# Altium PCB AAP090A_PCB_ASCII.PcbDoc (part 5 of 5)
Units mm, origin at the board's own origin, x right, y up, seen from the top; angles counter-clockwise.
Board outline 160 x 130 mm, 4 copper layers (Top Layer, Signal Layer 1, Signal Layer 2, Bottom Layer), stack 1.567 mm thick; 507 components, 275 nets, 1462 pads, 1041 vias.
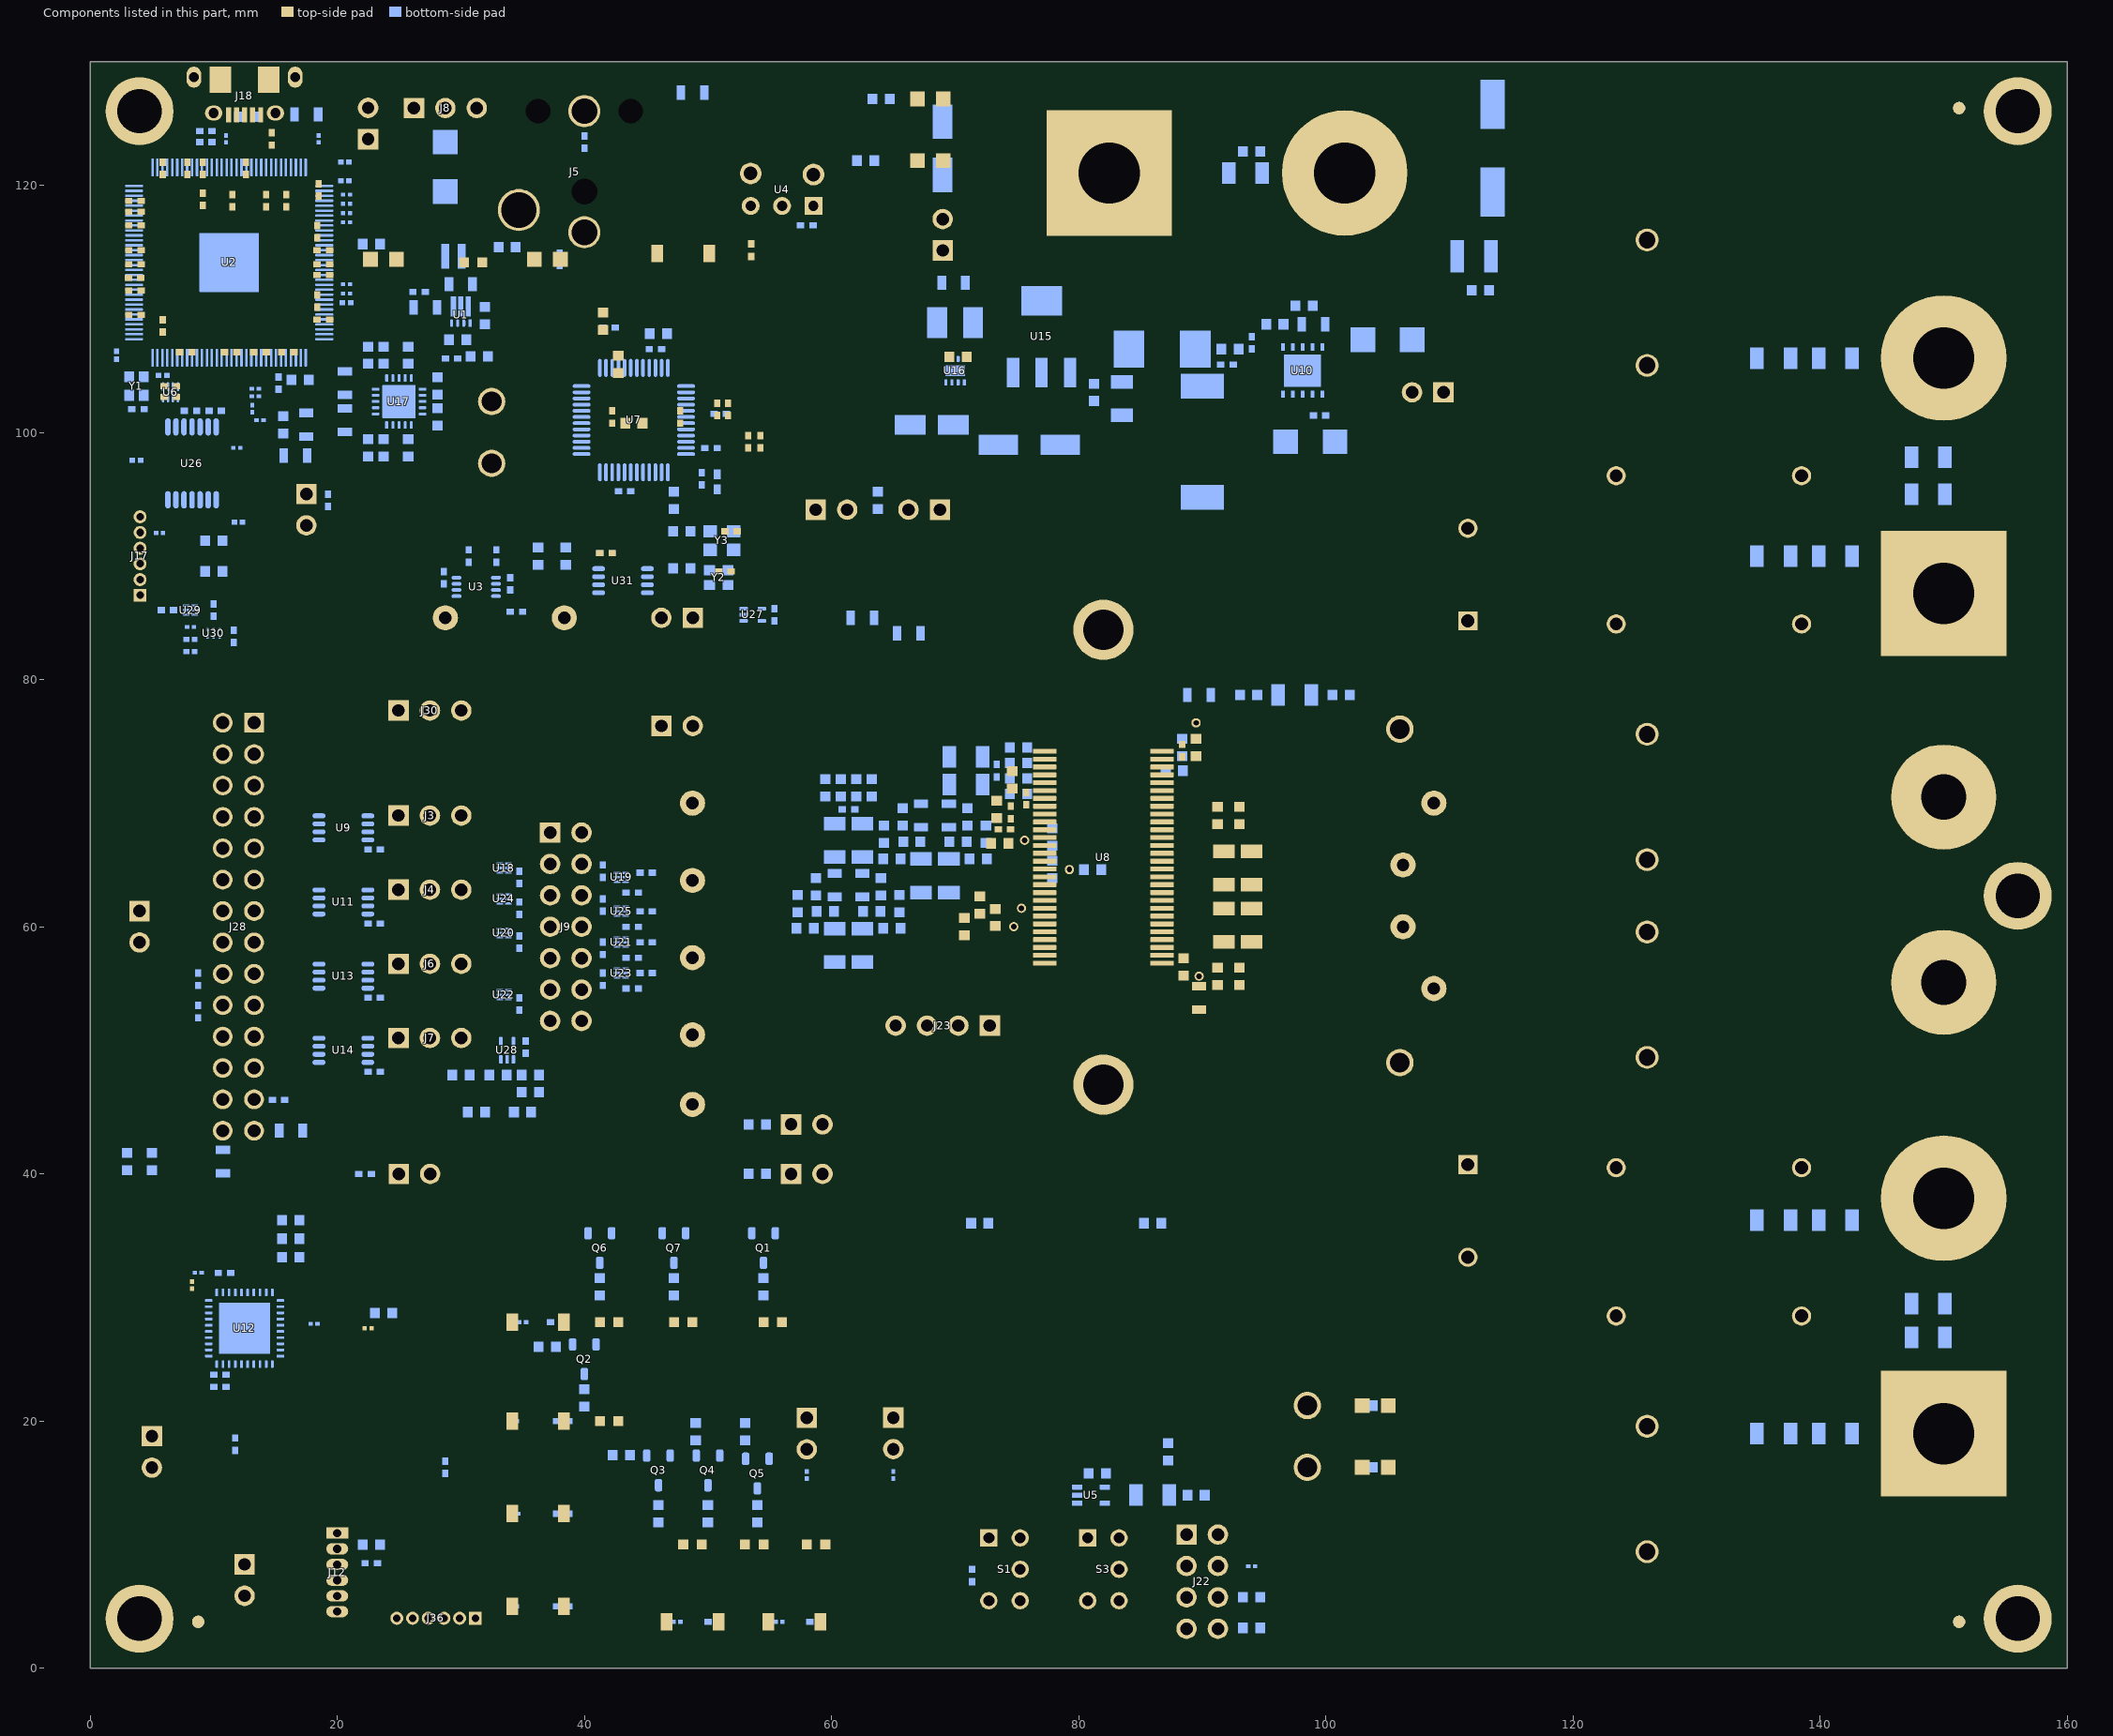
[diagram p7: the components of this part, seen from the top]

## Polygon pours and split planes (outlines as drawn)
GND on Top Layer "GND Top Copper" (solid, remove dead copper, pour order 55): 8.75,115 10,116.25 12.5,116.25 13.75,115 13.75,112.5 12.5,111.25 10,111.25 8.75,112.5
PVDD on Top Layer "PVDD Top Copper" (solid, remove dead copper, pour order 33): 85.85,60.65 89.05,60.65 90.8,58.9 90.8,58.15 93,58.15 110,41.15 110,40 111,39 114,39 116,41 116,46.25 112.75,46.25 99.6,59.4 91.75,59.4 89.75,61.65 88.8,61.65 88.225,61.075 85.85,61.075
SPK_OUTB- on Top Layer "OUT_D Top Copper" (solid, pour order 6): 88.75,60.45 85.375,60.45 85.25,60.325 85.25,60.125 85.375,60 87.9,60 88.1,59.8 88.1,59.6 88.275,59.425 89.025,59.425 89.2,59.6 89.2,60
SPK_OUTB+ on Top Layer "OUT_C Top Copper" (solid, pour order 4): 84.75,61.725 88.125,61.725 88.25,61.6 88.25,61.4 88.125,61.275 85.6,61.275 85.4,61.075 85.4,60.875 85.225,60.7 84.475,60.7 84.3,60.875 84.3,61.275
SPK_OUTA- on Top Layer "OUT_B Top Copper" (solid, pour order 2): 84.75,63.175 88.125,63.175 88.25,63.3 88.25,63.5 88.125,63.625 85.6,63.625 85.4,63.825 85.4,64.025 85.225,64.2 84.475,64.2 84.3,64.025 84.3,63.625
SPK_OUTA+ on Top Layer "OUT_A Top Copper" (solid, pour order 0): 88.75,64.45 85.375,64.45 85.25,64.575 85.25,64.775 85.375,64.9 87.9,64.9 88.1,65.1 88.1,65.3 88.275,65.475 89.025,65.475 89.2,65.3 89.2,64.9
PVDD on Top Layer "PVDD Top Copper" (solid, remove dead copper, pour order 35): 85.85,64.25 89.05,64.25 90.8,66 90.8,66.75 93.5,66.75 110,83.25 110,85.2 110.8,86 116,86 116,80 114,80 99.5,65.5 91.75,65.5 89.75,63.25 88.8,63.25 88.225,63.825 85.85,63.825
GND on Top Layer "GND Top Copper" (solid, remove dead copper, pour order 54): 7.5,129.5 7,129 7,124.75 5.25,123 2.75,123 0.5,120.75 0.5,8.5 2,7 6,7 7,6 7,2 8.5,0.5 145.5,0.5 159.5,14.5 159.5,115.5 145.5,129.5
OUTA+ on Top Layer "OUTA Top Copper" (solid, remove dead copper, pour order 9): 152.5,100.75 141.75,100.75 140.5,99.5 140.5,95.5 139.5,94.5 137.5,94.5 136,96 136,110 132.5,113.5 125.25,113.5 124,114.75 124,116.5 125.5,118 146,118 155.5,108.5 155.5,103.75
OUTA- on Top Layer "OUTB Top Copper" (solid, remove dead copper, pour order 13): 155.25,81.75 144.75,81.75 136.5,73.5 125.25,73.5 124,74.75 124,77 139.25,92.25 155.25,92.25
OUTB- on Top Layer "OUTD Top Copper" (solid, remove dead copper, pour order 21): 155.25,24.25 142,24.25 140.625,25.625 140.625,29.625 139.75,30.5 136.5,30.5 133,27 133,20 124,11 124,8.5 125.25,7.25 148.75,7.25 155.25,13.75
OUTB+ on Top Layer "OUTC Top Copper" (solid, remove dead copper, pour order 17): 152.5,43.5 144.5,43.5 136.5,51.5 125,51.5 124,50.5 124,48.5 139.75,32.75 152.75,32.75 156,36 156,40
PVDD on Top Layer "PVDD Top Copper" (solid, pour order 34): 101.375,126 108,126 122,112 122,47 114,39 111,39 110,40 110,43 112,45 114,45 115,46 115,110 109,116 101.375,116
GND-USB on Top Layer "GND-USB Top Copper" (solid, remove dead copper, pour order 52): 11.375,125 9.875,125 9.25,125.625 9.25,126.125 9.625,126.5 11.25,126.5 11.375,126.375
15V on Signal Layer 2 "15V Copper Layer 3" (solid, remove dead copper, pour order 50): 81.5,108 81.75,107.75 81.75,105 80.5,103.75 74.75,103.75 72.5,101.5 69,101.5 68.75,101.75 68.75,102.75 69.5,103.5 71.25,103.5 73.75,106 79,106 81,108
3.3V on Signal Layer 2 "3.3V Copper Layer 3" (solid, remove dead copper, pour order 43): 5,11.25 5,100 3.75,101.25 3.75,118.125 5.625,120 6.625,120 7.875,121.25 17.5,121.25 20.875,124.625 23.375,124.625 32.125,115.875 37.625,115.875 51.625,101.875 52.75,101.875 55,99.625 55,85 52.5,82.5 45,82.5 42.5,80 42.5,67.5 46.25,63.75 46.25,43.625 48.75,41.125 48.75,38.875 75.125,12.5 92.5,12.5 93.75,11.25 93.75,3.75 91.625,1.625 14.625,1.625
GND on Signal Layer 2 "GND Copper Layer 3" (solid, remove dead copper, pour order 85): 9.5,129.5 7,127 7,124.75 5.25,123 3,123 0.5,120.5 0.5,8.5 2,7 5.5,7 7,5.5 7,2 8.5,0.5 148,0.5 159.5,12 159.5,118 148,129.5
OUTA+ on Signal Layer 2 "OUTA Copper Layer 3" (solid, remove dead copper, pour order 10): 152.5,100.75 141.75,100.75 140.5,99.5 140.5,95.625 139.5,94.625 137.375,94.625 136,96 136,110 132.5,113.5 125,113.5 124,114.5 124,116.5 125.5,118 146,118 155.5,108.5 155.5,103.75
OUTB- on Signal Layer 2 "OUTD  Copper Layer 3" (solid, remove dead copper, pour order 22): 155.25,24.25 142,24.25 140.625,25.625 140.625,29.625 139.75,30.5 136.5,30.5 133,27 133,20 124,11 124,8.5 125.25,7.25 148.75,7.25 155.25,13.75
OUTB+ on Signal Layer 2 "OUTC Copper Layer 3" (solid, remove dead copper, pour order 18): 152.5,43.5 144.5,43.5 136.5,51.5 125,51.5 124,50.5 124,48 139.25,32.75 152.75,32.75 156,36 156,40
OUTA- on Signal Layer 2 "OUTB Copper Layer 3" (solid, remove dead copper, pour order 14): 155.25,81.75 144.75,81.75 136.5,73.5 125,73.5 124,74.5 124,77 138.25,91.25 144,91.25 144.875,92.125 155.25,92.125
1.0V on Signal Layer 2 "1.0V Copper Layer 3" (solid, remove dead copper, pour order 39): 25.5,112.25 16,112.25 16,110.625 23.875,110.625 24.875,109.625 25.625,109.625 25.75,109.75 25.75,112
15V on Bottom Layer "15V Bottom Copper" (solid, remove dead copper, pour order 49): 68.625,99.75 68.625,102.625 69.625,103.625 69.625,104.375 70.375,104.375 70.375,103.625 71.125,102.875 71.125,99.75
SW on Bottom Layer "SW Bottom Copper" (solid, remove dead copper, pour order 36): 70.075,105.75 70.075,106.95 70.75,107.625 72.25,107.625 71.05,106.425 70.55,106.425 70.425,106.3 70.425,105.75 70.375,105.7 70.125,105.7
1.8V on Bottom Layer "1.8V Bottom Copper" (solid, remove dead copper, pour order 42): 20,100.375 20.125,100.5 20.875,100.5 22.5,102.125 23.4,102.125 23.4,101.375 23.125,101.375 21.75,100 21.75,99 22.25,98.5 23,98.5 23,97.625 22,97.625 20,99.625
3.3V on Bottom Layer "3.3V Bottom Copper" (solid, remove dead copper, pour order 44): 20,104.5 20.25,104.25 21.5,104.25 22.875,102.875 23.4,102.875 23.4,103.6 22.25,104.75 22,104.75 21.75,105 21.75,106 22,106.25 23,106.25 23,107.5 22.75,107.75 20.75,107.75 20,107
5V on Bottom Layer "5V Bottom Copper" (solid, remove dead copper, pour order 46): 26.6,102.125 27.2,102.125 27.2,101.55 27.75,101 30.25,101 31.25,102 31.25,103.25 33.75,103.25 33.75,101.75 32,100 27.5,100 27.2,100.3 25.875,100.3 25.875,100.9 26.6,100.9
5V on Bottom Layer "5V Bottom Copper" (solid, remove dead copper, pour order 45): 26.6,102.875 27.2,102.875 27.2,103.45 27.75,104 30.25,104 31.25,103 31.25,101.75 33.75,101.75 33.75,103.75 32.5,105 27.5,105 27.2,104.7 25.875,104.7 25.875,104.1 26.6,104.1
OUTB- on Bottom Layer "OUTD Bottom Copper" (solid, pour order 24): 126,7.425 ccw(c126,9.425) 128,9.425 ccw(c126,9.425) 126,11.425 ccw(c126,9.425) 124,9.425 ccw(c126,9.425) 126,7.425
OUTB- on Bottom Layer "OUTD Bottom Copper" (solid, pour order 23): 138.5,26.5 ccw(c138.5,28.5) 140.5,28.5 ccw(c138.5,28.5) 138.5,30.5 ccw(c138.5,28.5) 136.5,28.5 ccw(c138.5,28.5) 138.5,26.5
OUTB+ on Bottom Layer "OUTC Bottom Copper" (solid, pour order 20): 138.5,38.5 ccw(c138.5,40.5) 140.5,40.5 ccw(c138.5,40.5) 138.5,42.5 ccw(c138.5,40.5) 136.5,40.5 ccw(c138.5,40.5) 138.5,38.5
OUTB+ on Bottom Layer "OUTC Bottom Copper" (solid, pour order 19): 126,47.425 ccw(c126,49.425) 128,49.425 ccw(c126,49.425) 126,51.425 ccw(c126,49.425) 124,49.425 ccw(c126,49.425) 126,47.425
OUTA- on Bottom Layer "OUTB Bottom Copper" (solid, pour order 16): 126,73.575 ccw(c126,75.575) 128,75.575 ccw(c126,75.575) 126,77.575 ccw(c126,75.575) 124,75.575 ccw(c126,75.575) 126,73.575
OUTA- on Bottom Layer "OUTB Bottom Copper" (solid, pour order 15): 138.5,82.5 ccw(c138.5,84.5) 140.5,84.5 ccw(c138.5,84.5) 138.5,86.5 ccw(c138.5,84.5) 136.5,84.5 ccw(c138.5,84.5) 138.5,82.5
OUTA+ on Bottom Layer "OUTA Bottom Copper" (solid, pour order 12): 138.5,94.5 ccw(c138.5,96.5) 140.5,96.5 ccw(c138.5,96.5) 138.5,98.5 ccw(c138.5,96.5) 136.5,96.5 ccw(c138.5,96.5) 138.5,94.5
OUTA+ on Bottom Layer "OUTA Bottom Copper" (solid, pour order 11): 126,113.575 ccw(c126,115.575) 128,115.575 ccw(c126,115.575) 126,117.575 ccw(c126,115.575) 124,115.575 ccw(c126,115.575) 126,113.575
15V on Bottom Layer "15V Bottom Copper" (solid, remove dead copper, pour order 51): 78.75,103.625 79.125,103.25 86.375,103.25 86.75,103.625 86.75,104 85.375,105.375 85.375,108.25 85.25,108.375 81,108.375 78.75,106.125 78.75,103.625
15V-VR on Bottom Layer "15V-VR Bottom Copper" (solid, remove dead copper, pour order 48): 91.875,102.75 91.875,106.125 92,106.25 92,107.25 91,108.25 88.125,108.25 88.125,102.75
VIN-PS on Bottom Layer "VIN-PS Bottom Copper" (solid, remove dead copper, pour order 38): 99.625,106.5 99.5,106.625 99.5,109.375 103.625,109.375 104,109 104,106.75 103.75,106.5
SW-PS on Bottom Layer "SW-PS Bottom Copper" (solid, remove dead copper, pour order 37): 99.625,103.437 99.5,103.312 99.5,98.187 99.625,98.062 101.625,98.062 101.75,98.187 101.75,100.187 101.75,100.437 100.125,102.062 100,102.187 100,102.812 100,103.313 99.875,103.437 99.625,103.437
SPK_OUTA+ on Bottom Layer "OUT_A Bottom Copper" (solid, remove dead copper, pour order 1): 85.25,64.5 85.5,64.25 89.5,64.25 93,67.75 113.75,67.75 120,74 120,96 127,103 127,106 126.625,106.375 122.375,106.375 114,98 114,76 110,72 96.25,72 95.25,71 93,71 87.5,65.5 85.75,65.5 85.25,65
SPK_OUTB+ on Bottom Layer "OUT_C Bottom Copper" (solid, remove dead copper, pour order 5): 127,60.125 127,59.125 125.875,58 92.875,58 90,60.875 85.5,60.875 85.25,60.625 84.5,60.625 84.25,60.875 84.25,61.125 84.25,61.375 85.25,62.375 91,62.375 91.5,61.875 125.25,61.875
SPK_OUTA- on Bottom Layer "OUT_B Bottom Copper" (solid, remove dead copper, pour order 3): 127,64.75 127,65.875 126,66.875 92.875,66.875 90,64 85.5,64 85.25,64.25 84.5,64.25 84.25,64 84.25,63.75 84.25,63.5 85.25,62.5 91,62.5 91.5,63 125.25,63
GND on Bottom Layer "GND Bottom Copper" (solid, remove dead copper, pour order 87): 9.5,129.5 7,127 7,124.75 5.25,123 3,123 0.5,120.5 0.5,8.5 2,7 6,7 7,6 7,2 8.5,0.5 145.5,0.5 159.5,14.5 159.5,115.5 145.5,129.5
SPK_OUTB- on Bottom Layer "OUT_D Bottom Copper" (solid, remove dead copper, pour order 8): 85.25,60.375 85.5,60.625 89.5,60.625 93,57.125 113.75,57.125 120,50.875 120,28.875 127,21.875 127,18.875 126.625,18.5 122.375,18.5 114,26.875 114,48.875 110,52.875 96.25,52.875 95.25,53.875 93,53.875 87.5,59.375 85.75,59.375 85.25,59.875
5V on Bottom Layer "5V Bottom Copper" (solid, remove dead copper, pour order 47): 30.625,115.625 30.625,111.25 30.375,111 30.375,109.375 31.125,109.375 31.375,109.625 32.375,109.625 32.375,110.625 32.125,110.625 31.75,111 31.75,116.5 29.75,118.5 29.75,120.5 27.75,120.5 27.75,118.5
1.0V on Bottom Layer "1.0V Bottom Copper" (solid, remove dead copper, pour order 40): 29.125,115.25 29.125,113.25 28,113.25 26.5,111.75 26.5,110 27.375,109.125 29.375,109.125 29.375,106.875 29.125,106.625 29.125,105.75 28.375,105.75 28.375,106.625 25.625,109.375 25.375,109.375 24.875,109.875 24.875,112 28.125,115.25
GND-USB on Bottom Layer "GND-USB Bottom Copper" (solid, remove dead copper, pour order 53): 16.875,125 14.875,125 14.25,125.625 14.25,126.125 14.625,126.5 16.75,126.5 16.875,126.375
OUTB- on Signal Layer 1 "OUTD Copper Layer 2" (solid, pour order 32): 126,7.425 ccw(c126,9.425) 128,9.425 ccw(c126,9.425) 126,11.425 ccw(c126,9.425) 124,9.425 ccw(c126,9.425) 126,7.425
OUTB- on Signal Layer 1 "OUTD Copper Layer 2" (solid, pour order 31): 138.5,26.5 ccw(c138.5,28.5) 140.5,28.5 ccw(c138.5,28.5) 138.5,30.5 ccw(c138.5,28.5) 136.5,28.5 ccw(c138.5,28.5) 138.5,26.5
OUTB+ on Signal Layer 1 "OUTC Copper Layer 2" (solid, pour order 30): 138.5,38.5 ccw(c138.5,40.5) 140.5,40.5 ccw(c138.5,40.5) 138.5,42.5 ccw(c138.5,40.5) 136.5,40.5 ccw(c138.5,40.5) 138.5,38.5
OUTB+ on Signal Layer 1 "OUTC Copper Layer 2" (solid, pour order 29): 126,47.425 ccw(c126,49.425) 128,49.425 ccw(c126,49.425) 126,51.425 ccw(c126,49.425) 124,49.425 ccw(c126,49.425) 126,47.425
OUTA- on Signal Layer 1 "OUTB Copper Layer 2" (solid, pour order 28): 126,73.575 ccw(c126,75.575) 128,75.575 ccw(c126,75.575) 126,77.575 ccw(c126,75.575) 124,75.575 ccw(c126,75.575) 126,73.575
OUTA- on Signal Layer 1 "OUTB Copper Layer 2" (solid, pour order 27): 138.5,82.5 ccw(c138.5,84.5) 140.5,84.5 ccw(c138.5,84.5) 138.5,86.5 ccw(c138.5,84.5) 136.5,84.5 ccw(c138.5,84.5) 138.5,82.5
OUTA+ on Signal Layer 1 "OUTA Copper Layer 2" (solid, pour order 26): 138.5,94.5 ccw(c138.5,96.5) 140.5,96.5 ccw(c138.5,96.5) 138.5,98.5 ccw(c138.5,96.5) 136.5,96.5 ccw(c138.5,96.5) 138.5,94.5
OUTA+ on Signal Layer 1 "OUTA Copper Layer 2" (solid, pour order 25): 126,113.575 ccw(c126,115.575) 128,115.575 ccw(c126,115.575) 126,117.575 ccw(c126,115.575) 124,115.575 ccw(c126,115.575) 126,113.575
GND on Signal Layer 1 "GND Copper Layer 2" (solid, remove dead copper, pour order 56): 12,129.5 0.5,118 0.5,8.5 2,7 6,7 7,6 7,2 8.5,0.5 148,0.5 159.5,12 159.5,118 148,129.5

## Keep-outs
Keep-Out Layer:
  lines w0.254: -0.25,-0.25 160.25,-0.25 160.25,130.25 -0.25,130.25 -0.25,-0.25

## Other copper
Top Layer:
  text ".Layer_Name" at 14.656,-21.806 h1.52
Signal Layer 1:
  text ".Layer_Name" at 14.656,-21.806 h1.52
Signal Layer 2:
  text ".Layer_Name" at 14.656,-21.806 h1.52
Bottom Layer:
  text ".Layer_Name" at 14.656,-21.806 h1.52

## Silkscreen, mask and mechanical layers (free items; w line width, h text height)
Top Overlay:
  lines w0.2: 20.5,43.5 20.5,70.75 32,70.75 32,43.5 20.5,43.5 ; 33,24 58,24 58,31.5 33,31.5 33,24 ; 45,0 45,12.25 62.5,12.25 62.5,0 45,0
  lines w0.25: 0,40 16.375,40 16.375,80 0,80 ; 24,47.275 24,46.775 27,46.775 27,47.275 ; 25.5,46.275 25.5,46.775 ; 28,47.275 28,46.775 31,46.775 31,47.275 ; 29.5,46.275 29.5,46.775 ; 29.5,49 30.5,49 ; 29.5,55 30.5,55 ; 29.5,61 30.5,61 ; 29.5,67 30.5,67 ; 29.75,48.5 30.25,48.5 ; 29.75,54.5 30.25,54.5 ; 29.75,60.5 30.25,60.5 ; 29.75,66.5 30.25,66.5 ; 30,49 30,49.25 ; 30,55 30,55.25 ; 30,61 30,61.25 ; 30,67 30,67.25 ; 68.81,104.815 63.8,104.815 63.8,26.435 100.2,26.435 100.2,104.815 ; 71.125,104.815 96.25,104.815 ; 30,48 30,48 ; 30,54 30,54 ; 30,60 30,60 ; 30,66 30,66
  lines w0.254: 19.25,32.5 33.25,32.5 33.25,42 19.25,42 19.25,32.5 ; 46.75,14.5 46.75,23.5 60.25,23.5 60.25,14.5 46.75,14.5
  text "USB" at 17,126 h1.25
  text "PVDD MAX = 36V" at 110.25,120.125 h1.5
  text "OUTA+" at 145.5,114.625 h2
  text "USB" at 22,111.25 h1.25
  text "SPDIF" at 28.5,111.25 h1.25
  text "SPDIF" at 34.75,111.25 h1.25
  text "SPDIF" at 45.75,111.25 h1.25
  text "GND" at 77.5,110.625 h1.75
  text "PVDD" at 100.25,110.625 h1.75
  text "READY" at 21.25,109.5 h1.25
  text "LOCK" at 28.75,109.5 h1.25
  text "READY" at 34.25,109.5 h1.25
  text "RESET" at 45.25,109.5 h1.25
  text "XMOS" at 15,89.25 h1.4
  text "DISABLE" at 13.75,87.25 h1.4
  text "IN = 22.5792MHz / OUT = 24.576MHz" at 39.25,79.25 h1.25
  text "1" at 12.875,78.25 h1.25
  text "OUTA-" at 145.5,76.5 h2
  text "SDOUT" at 21.75,74.5 h1.25
  text "SDIN" at 28.75,74.5 h1.25
  text "IN = XTAL / OUT = SPDIF" at 50.5,74.25 h1.25
  text "MCLK" at 23.75,66 h1.25
  text "SCLK" at 23.75,60 h1.25
  text "LRCK" at 23.75,54 h1.25
  text "SDIN" at 23.75,48 h1.25
  text "AUDIO INTERFACE BOARD" at 8.375,47 h1.5 r90
  text "OUTB+" at 145.5,46.625 h2
  text "MUX" at 23,44.25 h1.5
  text "EXT" at 28,44.25 h1.5
  text "28" at 9.75,40.75 h1
  text "27" at 12.5,40.75 h1
  text "IN=PBTL / OUT=BTL" at 46.25,40 h1.25
  text "I2S SELECT" at 20.125,36.75 h1.5
  text "IN: SRC I2S" at 21,34.75 h1.25
  text "OUT: AIB I2S" at 20.375,33 h1.25
  text "I2C ADR1" at 67,19.5 h1.25
  text "IN=BTL" at 49.25,19.25 h1.25
  text "SLAVE" at 6.875,17.75 h1.4
  text "OUT=PBTL" at 47.25,17.25 h1.25
  text "IN=0/OUT=1" at 66.75,17.25 h1
  text "ENABLE" at 6.875,15.75 h1.4
  text "1" at 17.75,10.5 h1.25
  text "SLAVE MODE" at 93.25,10.25 h1.25
  text "GND" at 21.75,9.25 h1
  text "NORMAL" at 64.25,9.25 h1.25
  text "OUTB-" at 145.5,8.375 h2
  text "TDIO" at 21.75,7.875 h1
  text "MASTER" at 93.25,7.75 h1.25
  text "MODE" at 100.5,7.75 h1.25
  text "TCK" at 21.75,6.5 h1
  text "MASTER" at 93.25,5.25 h1.25
  text "MODE" at 100.5,5.25 h1.25
  text "AM1" at 105.75,5.25 h1.25
  text "VCC-TOOL" at 21.75,5.125 h1
  text "MUTE" at 66.75,5 h1.25
  text "TAS3251EVM" at 110.5,4.25 h2
  text "MASTER" at 93.25,2.75 h1.25
  text "MODE" at 100.5,2.75 h1.25
  text "AM2" at 105.75,2.75 h1.25
  text "JTAG" at 9.875,2.5 h1.5
  text "DAC" at 72.25,2.5 h1.25
  text "AMP" at 80.25,2.5 h1.25
  text "AAP090A" at 113.75,1.5 h1.5
  text "PWR" at 10.625,0.5 h1.5
  text "PROG SEL" at 53.25,0.5 h1.25
  text "MUTE" at 71.5,0.5 h1.25
  text "RESET" at 79.5,0.5 h1.25
  text ".Layer_Name" at 14.656,-21.806 h1.52
Bottom Overlay:
  lines w0.25: 0.5,37.5 1.75,37.5 ; 6.25,37.5 56.75,37.5 56.75,0.5 ; 50.75,37.5 50.75,82 56.25,82 56.25,84 ; 56.25,86.5 56.25,112.5 60,112.5 60,129.5 ; 56.75,65.5 58.75,65 ; 63.5,54.75 53,54.75 53,75.5 53,78.5 80,78.5 80,72.5 84.125,68.375 84.125,62.5 76.375,54.75 74.5,54.75 ; 73.25,74.625 73.375,73.875 ; 75.625,67.875 75.625,68.25 ; 99.875,109.875 99.875,110.75
  text "USB" at 25,120.75 h1.5 r270
  text "PVDD" at 31,119.5 h1.5 r270
  text "POST FILTER FEEDBACK" at 78.5,79.125 h1.5
  text "DIGITAL" at 42.25,78 h1.75
  text "INPUT" at 41.75,75.5 h1.75
  text "IOM" at 65.875,46.75 h1.5
  text "GND" at 70.875,46.75 h1.5
  text "IOP" at 74.875,46.625 h1.5
  text "MSP430" at 30,22 h1.5
  text "CONTROL" at 30.5,19.75 h1.5
  text ".Layer_Name" at 14.656,-21.806 h1.52
Top Paste:
  text ".Layer_Name" at 14.656,-21.806 h1.52
Bottom Paste:
  text ".Layer_Name" at 14.656,-21.806 h1.52
Top Solder:
  text ".Layer_Name" at 14.656,-21.806 h1.52
Bottom Solder:
  text ".Layer_Name" at 14.656,-21.806 h1.52
Drill Guide:
  text ".Layer_Name" at 165.25,89 h1.52
M1 Board Outline:
  the board outline again, w0.254
  text ".Layer_Name" at 57.25,-21.875 h1.52
M2 Board Dimensions:
  rectangle: 3.175,-10.16 12.7,-6.985
  rectangle: 0,-6.985 3.175,-3.81
  lines w0.178: 0,-6.985 25.4,-6.985 ; 3.175,-10.16 3.175,-3.81 ; 6.35,-10.16 6.35,-3.81 ; 12.7,-10.16 12.7,-3.81 ; 19.05,-10.16 19.05,-3.81 ; 0,-10.16 0,-3.81 25.4,-3.81 25.4,-10.16 0,-10.16
  text ".Layer_Name" at 86.125,-21.875 h1.52
M3 3D STEP Top:
  text ".Layer_Name" at 14.656,-21.806 h1.52
M4 3D STEP Bottom:
  text ".Layer_Name" at 14.656,-21.806 h1.52
M5 Assembly Top:
  lines w0.254: -7.417,-23.626 160.223,-23.626 ; -7.417,-18.462 160.274,-18.462 ; -7.417,-13.297 -7.417,-28.791 94.31,-28.791 160.274,-28.791 160.274,-13.297 -7.404,-13.297 -7.404,-28.791 32.614,-28.791 ; 55.194,-28.791 55.194,-13.297 ; 87.376,-18.462 87.376,-13.297 ; 108.712,-18.462 108.712,-13.297 ; 124.511,-28.956 124.511,-23.804
  text "COMPONENTS MARKED 'DNP' SHOULD NOT BE POPULATED." at 29.299,-8.09 h1.52
  text "ASSEMBLY VARIANT:" at 29.286,-11.024 h1.52
  text ".VariantName" at 55.601,-11.024 h1.52
  text "PCB VIEWED FROM TOP SIDE" at -5.804,-16.654 h1.52
  text "BOARD #:" at 57.099,-16.654 h1.52
  text ".PRJ_Number" at 70.955,-16.654 h1.52
  text "REV:" at 92.405,-16.654 h1.52
  text ".PCB_Rev" at 99.809,-16.654 h1.52
  text "SVN REV:" at 113.69,-16.654 h1.52
  text ".VersionControl_RevNumber" at 126.543,-16.654 h1.52
  text "PLOT NAME =" at -5.804,-27.034 h1.52
  text ".plot_File_Name" at 14.656,-27.034 h1.52
  text "GENERATED    :" at 57.15,-27.034 h1.52
  text ".Print_Date" at 79.235,-27.034 h1.52
  text ".Print_Time" at 97.752,-27.034 h1.52
  text "TEXAS INSTRUMENTS" at 129.87,-27.034 h1.52
M6 Assembly Bottom:
  lines w0.254: -7.429,-18.474 160.261,-18.474 ; -7.379,-23.639 160.261,-23.639 ; 28.334,-28.969 28.334,-23.817 ; 44.133,-18.474 44.133,-13.31 ; 65.468,-18.474 65.468,-13.31 ; 97.65,-28.804 97.65,-13.31 ; 120.231,-28.804 160.249,-28.804 160.249,-13.31 -7.429,-13.31 -7.429,-28.804 58.534,-28.804 160.261,-28.804 160.261,-13.31
  text "COMPONENTS MARKED 'DNP' SHOULD NOT BE POPULATED." at 154.991,-8.077 h1.52
  text ".VariantName" at 128.473,-11.024 h1.52
  text "ASSEMBLY VARIANT:" at 154.864,-11.024 h1.52
  text ".VersionControl_RevNumber" at 26.302,-16.667 h1.52
  text "SVN REV:" at 39.154,-16.667 h1.52
  text ".PCB_Rev" at 53.035,-16.667 h1.52
  text "REV:" at 60.439,-16.667 h1.52
  text ".PRJ_Number" at 81.89,-16.667 h1.52
  text "BOARD #:" at 95.745,-16.667 h1.52
  text "PCB VIEWED FROM BOTTOM SIDE" at 158.648,-16.667 h1.52
  text "TEXAS INSTRUMENTS" at 22.974,-27.047 h1.52
  text ".Print_Time" at 55.093,-27.047 h1.52
  text ".Print_Date" at 73.609,-27.047 h1.52
  text "GENERATED    :" at 95.694,-27.047 h1.52
  text ".plot_File_Name" at 138.189,-27.047 h1.52
  text "PLOT NAME =" at 158.648,-27.047 h1.52
M9 Title Sheet:
  lines w0.254: -12.484,26.454 -7.404,26.454 ; -12.484,86.779 -7.404,86.779 ; -12.484,147.104 -7.404,147.104 ; 51.016,-33.871 51.016,-28.791 ; 51.016,202.349 51.016,207.429 ; 114.516,-33.871 114.516,-28.791 ; 114.516,202.349 114.516,207.429 ; 160.553,-28.791 160.553,-13.297 287.109,-13.297 ; 178.016,-33.871 178.016,-28.791 ; 178.016,202.349 178.016,207.429 ; 241.516,-33.871 241.516,-28.791 ; 241.516,202.349 241.516,207.429 ; 287.109,-28.791 287.109,-13.297 ; 287.109,-20.917 363.309,-20.917 ; 287.109,-5.677 363.309,-5.677 ; 287.134,9.411 363.334,9.411 ; 305.016,-33.871 305.016,-28.791 ; 305.016,202.349 305.016,207.429 ; 325.336,-28.537 325.336,-13.297 ; 363.309,-13.297 287.109,-13.297 ; 363.309,1.943 287.109,1.943 ; 363.436,1.689 363.436,-28.791 ; 363.436,22.123 287.134,22.123 287.109,22.123 287.109,9.411 287.109,1.943 ; 363.436,26.454 368.516,26.454 ; 363.436,86.779 368.516,86.779 ; 363.436,147.104 368.516,147.104 ; 287.109,-13.297 287.109,1.943 ; 363.436,-28.791 -7.404,-28.791 -7.404,202.349 363.436,202.349 363.436,-28.791 ; -12.484,-33.871 368.516,-33.871 368.516,207.429 -12.484,207.429 -12.484,-33.871
  text "1" at 18.792,204.127 h1.78
  text "2" at 82.182,204.127 h1.78
  text "3" at 145.411,204.127 h1.78
  text "4" at 209.08,204.127 h1.78
  text "5" at 272.555,204.127 h1.78
  text "6" at 336.182,204.127 h1.78
  text "A" at -10.579,175.095 h1.78
  text "A" at 365.341,175.095 h1.78
  text "B" at -10.579,114.643 h1.78
  text "B" at 365.341,114.643 h1.78
  text "C" at -10.579,54.318 h1.78
  text "C" at 365.341,54.318 h1.78
  text "PROJECT TITLE:" at 288.125,7.048 h1.14
  text ".PRJ_Title" at 289.395,3.662 h1.78
  text "DESIGNED FOR:" at 288.125,-0.597 h1.14
  text ".PRJ_Customer" at 289.395,-4.153 h1.78
  text "D" at -10.579,-5.88 h1.78
  text "D" at 365.341,-5.88 h1.78
  text "FILE NAME:" at 288.125,-8.217 h1.14
  text ".PCB_File_Name_No_Path" at 289.395,-11.265 h1.78
  text "Texas Instruments (TI) and/or its licensors do not warrant the accuracy or completeness of this specification" at 161.9,-15.376 h1.14
  text "ENGINEER:" at 288.125,-15.583 h1.14
  text "LAYOUT BY:" at 326.352,-15.583 h1.14
  text "or any information contained therein. TI and/or its licensors do not warrant that this design will meet" at 160.757,-18.237 h1.14
  text ".PRJ_Engineer" at 289.395,-19.52 h1.78
  text ".PCB_Layout" at 327.635,-19.52 h1.78
  text "the specifications, will be suitable for your application or fit for any particular purpose, or will operate in" at 160.757,-21.099 h1.14
  text "ALTIUM DESIGNER VERSION:" at 326.352,-23.457 h1.14
  text "an implementation. TI and/or its licensors do not warrant that the design is production worthy. You should" at 160.757,-23.961 h1.14
  text "completely validate and test your design implementation to confirm the system functionality for your application." at 161.9,-26.822 h1.14
  text ".print_Scale" at 289.395,-26.843 h1.78
  text ".Application_BuildNumber" at 327.635,-26.843 h1.78
  text "1" at 18.792,-32.093 h1.78
  text "2" at 82.182,-32.093 h1.78
  text "3" at 145.411,-32.093 h1.78
  text "4" at 209.08,-32.093 h1.78
  text "5" at 272.555,-32.093 h1.78
  text "6" at 336.182,-32.093 h1.78
M10 Fab Notes:
  drawing of 189 lines, arcs and shapes, not listed
  text ".Layer_Name" at 287.5,164.75 h1.52
  text "DESIGN INFORMATION" at 314.503,161.447 h1.52
  text "MIN. TRACK WIDTH:" at 298.131,158.091 h1.52
  text "6" at 325.976,158.091 h1.52
  text "MIL" at 329.907,158.091 h1.52
  text "MIN. CLEARANCE:" at 298.131,154.938 h1.52
  text "0.1" at 324.452,154.938 h1.52
  text "mm" at 329.907,154.938 h1.52
  text "MIN. VIA PAD SIZE:" at 298.131,151.785 h1.52
  text "18" at 325.214,151.785 h1.52
  text "MIL" at 329.907,151.785 h1.52
  text "0.05mm (2MIL)" at 315.784,148.486 h1.52
  text "MINIMUM ANNULAR RING" at 289.769,148.277 h1.52
  text "EXTERNAL" at 333.768,148.277 h1.52
  text "PER" at 294.849,145.48 h1.52
  text "IPC-D-275 CLASS 2 LEVEL C" at 300.437,145.48 h1.52
  text "MIL, HOLES" at 338.238,142.928 h1.52
  text "+/-" at 328.27,142.709 h1.52
  text "+/-" at 349.961,142.709 h1.52
  text "REGISTRATION TOLERANCES:" at 289.769,142.682 h1.52
  text "METAL" at 320.243,142.682 h1.52
  text "5" at 334.879,142.683 h1.52
  text "3" at 356.037,142.683 h1.52
  text "MIL" at 358.99,142.682 h1.52
  text "HOLE SIZE TOLERANCE (UNLESS OTHERWISE SPECIFIED):" at 289.769,140.185 h1.52
  text "+/-" at 349.961,140.112 h1.52
  text "3" at 356.037,140.085 h1.52
  text "MIL" at 358.99,140.085 h1.52
  text "MATERIAL:" at 287.87,136.589 h1.52
  text "FR-4 High Tg" at 312.926,133.324 h1.52
  text "X" at 309.257,133.122 h1.52
  text "FR-408" at 298.563,133.007 h1.52
  text "OTHER" at 336.358,133.007 h1.52
  text "62 MIL (1.6mm) +/-10%" at 306.694,129.374 h1.52
  text "X" at 303.643,129.312 h1.52
  text "THICKNESS:" at 289.769,129.165 h1.52
  text "OTHER" at 339.33,129.165 h1.52
  text "TOLERANCE:" at 289.769,125.652 h1.52
  text "X" at 311.314,125.652 h1.52
  text "ANSI IPC-6012 TYPE 3 CLASS 2" at 315.836,125.652 h1.52
  text "OTHER +/-" at 315.835,121.989 h1.52
  text "BOW & TWIST:" at 289.769,118.302 h1.52
  text "X" at 311.314,118.302 h1.52
  text "ANSI IPC-6012 TYPE 3 CLASS 2" at 315.836,118.302 h1.52
  text "OTHER +/-" at 315.835,114.576 h1.52
  text "DRILLING:" at 287.87,111.258 h1.52
  text "NC_DRILL FILES" at 332.599,108.586 h1.52
  text "REFERENCE:" at 289.769,108.486 h1.52
  text "X" at 306.463,108.484 h1.52
  text "AS SHOWN" at 310.984,108.486 h1.52
  text "X" at 329.348,108.486 h1.52
  text "OTHER" at 340.168,104.873 h1.52
  text "PTH COPPER THICKNESS:" at 289.761,104.783 h1.52
  text "X" at 318.697,104.783 h1.52
  text "20-30 um" at 321.948,104.783 h1.52
  text "BOARD FINISH:" at 287.87,101.034 h1.52
  text "SILKSCREEN:" at 291.812,98.237 h1.52
  text "X" at 316.14,98.237 h1.52
  text "TOP" at 319.112,98.237 h1.52
  text "X" at 329.094,98.237 h1.52
  text "BOTTOM" at 332.091,98.237 h1.52
  text "SILKSCREEN COLOR:" at 291.812,94.295 h1.52
  text "X" at 316.115,94.295 h1.52
  text "WHITE" at 319.112,94.295 h1.52
  text "OTHER" at 332.091,94.295 h1.52
  text "X" at 319.442,90.652 h1.52
  text "BLUE" at 322.439,90.652 h1.52
  text "OTHER" at 338.136,90.652 h1.52
  text "SOLDER RESIST COLOR:" at 291.812,90.477 h1.52
  text "X" at 319.442,86.734 h1.52
  text "MATTE" at 322.439,86.734 h1.52
  text "SEMI-GLOSS" at 338.125,86.717 h1.52
  text "IMMERSION GOLD (ENIG)" at 314.819,82.345 h1.52
  text "ENEPIG" at 348.793,82.162 h1.52
  text "SURFACE FINISH:" at 287.87,82.136 h1.52
  text "X" at 310.298,82.136 h1.52
  text "IMM. TIN/SILVER OR EQUIV" at 296.24,78.649 h1.52
  text "OTHER" at 332.599,78.549 h1.52
  text "ARRAY/PANEL:" at 287.87,74.602 h1.52
  text "CUT AND TRIM PER M1 BOARD OUTLINE" at 314.819,74.393 h1.52
  text "N.C. ROUTE" at 314.819,70.94 h1.52
  text "X" at 332.295,70.94 h1.52
  text "V. SCORE" at 336.816,70.94 h1.52
  text "CERTIFICATION:" at 287.87,67.66 h1.52
  text "MATERIALS AND WORKMANSHIP FOR ALL PCBS" at 306.285,67.66 h1.52
  text "TO MEET OR EXCEED THE REQUIREMENTS OF:" at 306.285,65.271 h1.52
  text "X" at 297.078,62.003 h1.52
  text "ANSI IPC-A-600F CLASS ->" at 300.329,62.003 h1.52
  text "X" at 342.188,62.003 h1.52
  text "2" at 344.982,62.003 h1.52
  text "1" at 336.981,61.965 h1.52
  text "3" at 353.973,61.965 h1.52
  text "X" at 317.702,58.252 h1.52
  text "RoHS" at 320.953,58.252 h1.52
  text "OTHER" at 337.321,58.252 h1.52
  text "PER ORDER" at 347.407,58.252 h1.52
  text "ALL BOARDS MUST MEET OR EXCEED UL94-V0 REQUIREMENTS." at 288.569,54.345 h1.52
  text "PCB MUST BEAR THE UL94V-0 UL REGISTERED MATERIAL ID NUMBER" at 288.569,51.397 h1.52
  text "ADDITIONAL REQUIREMENTS:" at 287.87,47.094 h1.52
  text "MICROSECTION:" at 289.769,44.373 h1.52
  text "YES" at 312.775,44.373 h1.52
  text "REQUIRED" at 334.657,40.707 h1.52
  text "BARE BOARD ELEC. TEST:" at 289.769,40.634 h1.52
  text "NONE" at 322.935,40.634 h1.52
  text "X" at 331.66,40.634 h1.52
  text "PER ORDER" at 349.693,40.634 h1.52
  text "XX MIL VIAS REQUIRE NON-CONDUCTIVE FILL AND PLANARIZE" at 294.04,35.428 h1.5
  text "XX MIL VIAS REQUIRE CONDUCTIVE FILL AND PLANARIZE" at 294.243,32.787 h1.52
  text "OUTER XX MIL VIAS REQUIRE 50 OHM SINGLE-ENDED IMPEDANCE" at 294.218,28.637 h1.47
  text "LAYER 2 & 3 (INNER LAYERS) XX MIL WIDE, XX MIL SPACE / TRACES REQUIRE 100 OHM DIFFERENTIAL IMPEDANCE" at 294.015,22.65 h1.52
M11 Gerber Information:
  lines w0.254: -7.417,-23.626 160.223,-23.626 ; -7.417,-18.462 160.274,-18.462 ; -7.417,-13.297 -7.417,-28.791 94.31,-28.791 160.274,-28.791 160.274,-13.297 -7.404,-13.297 -7.404,-28.791 32.614,-28.791 ; 55.194,-28.791 55.194,-13.297 ; 87.376,-18.462 87.376,-13.297 ; 108.712,-18.462 108.712,-13.297 ; 124.511,-28.956 124.511,-23.804
  text "ALL ARTWORK VIEWED FROM TOP SIDE" at -5.804,-16.654 h1.52
  text "BOARD #:" at 57.099,-16.654 h1.52
  text ".PRJ_Number" at 70.955,-16.654 h1.52
  text "REV:" at 92.405,-16.654 h1.52
  text ".PCB_Rev" at 99.809,-16.654 h1.52
  text "SVN REV:" at 113.69,-16.654 h1.52
  text ".VersionControl_RevNumber" at 126.543,-16.654 h1.52
  text "LAYER NAME =" at -5.804,-21.806 h1.52
  text "PLOT NAME =" at -5.804,-27.034 h1.52
  text ".plot_File_Name" at 14.656,-27.034 h1.52
  text "GENERATED    :" at 57.15,-27.034 h1.52
  text ".Print_Date" at 79.235,-27.034 h1.52
  text ".Print_Time" at 97.752,-27.034 h1.52
  text "TEXAS INSTRUMENTS" at 129.87,-27.034 h1.52
M12 Stackup:
  drawing of 295 lines, arcs and shapes, not listed
  text ".Layer_Name" at 165.5,133 h1.52
  text "Layer" at 166.715,129.481 h1.52
  text "Name" at 177.126,129.481 h1.52
  text "Material" at 200.996,129.481 h1.52
  text "Thickness" at 222.834,129.481 h1.52
  text "Constant" at 239.34,129.481 h1.52
  text "Board Layer Stack" at 253.814,129.481 h1.52
  text "1" at 166.715,126.433 h1.52
  text "Top Overlay" at 177.126,126.433 h1.52
  text "2" at 166.715,123.385 h1.52
  text "Top Solder" at 177.126,123.385 h1.52
  text "Solder Resist" at 200.996,123.385 h1.52
  text "0.40mil" at 222.834,123.385 h1.52
  text "3.5" at 239.34,123.385 h1.52
  text "3" at 166.715,120.337 h1.52
  text "Top Layer" at 177.126,120.337 h1.52
  text "Copper" at 200.996,120.337 h1.52
  text "2.74mil" at 222.834,120.337 h1.52
  text "4" at 166.715,117.289 h1.52
  text "Dielectric 1" at 177.126,117.289 h1.52
  text "FR-4" at 200.996,117.289 h1.52
  text "8.00mil" at 222.834,117.289 h1.52
  text "4.2" at 239.34,117.289 h1.52
  text "5" at 166.715,114.241 h1.52
  text "Signal Layer 1" at 177.126,114.241 h1.52
  text "Copper" at 200.996,114.241 h1.52
  text "1.40mil" at 222.834,114.241 h1.52
  text "6" at 166.715,111.193 h1.52
  text "Dielectric 2" at 177.126,111.193 h1.52
  text "FR-4" at 200.996,111.193 h1.52
  text "37.42mil" at 222.834,111.193 h1.52
  text "4.2" at 239.34,111.193 h1.52
  text "7" at 166.715,108.145 h1.52
  text "Signal Layer 2" at 177.126,108.145 h1.52
  text "Copper" at 200.996,108.145 h1.52
  text "1.40mil" at 222.834,108.145 h1.52
  text "8" at 166.715,105.097 h1.52
  text "Dielectric 3" at 177.126,105.097 h1.52
  text "FR-4" at 200.996,105.097 h1.52
  text "8.00mil" at 222.834,105.097 h1.52
  text "4.2" at 239.34,105.097 h1.52
  text "9" at 166.715,102.049 h1.52
  text "Bottom Layer" at 177.126,102.049 h1.52
  text "Copper" at 200.996,102.049 h1.52
  text "2.74mil" at 222.834,102.049 h1.52
  text "10" at 166.715,99.001 h1.52
  text "Bottom Solder" at 177.126,99.001 h1.52
  text "Solder Resist" at 200.996,99.001 h1.52
  text "0.40mil" at 222.834,99.001 h1.52
  text "3.5" at 239.34,99.001 h1.52
  text "11" at 166.715,95.953 h1.52
  text "Bottom Overlay" at 177.126,95.953 h1.52
M13 Component Bodies Top:
  text ".Layer_Name" at 14.656,-21.806 h1.52
M14 Component Bodies Bottom:
  text ".Layer_Name" at 14.656,-21.806 h1.52
M15 Courtyards Top:
  text ".Layer_Name" at 14.656,-21.806 h1.52
M16 Courtyards Bottom:
  text ".Layer_Name" at 14.656,-21.806 h1.52
Drill Drawing:
  drawing of 171 lines, arcs and shapes, not listed
  text "Symbol" at 167.047,85.862 h1.83
  text "Quantity" at 174.681,85.862 h1.83
  text "Finished Hole Size" at 183.114,85.862 h1.83
  text "Plated" at 199.283,85.862 h1.83
  text "Hole Type" at 205.865,85.862 h1.83
  text "Drill Layer Pair" at 215.394,85.862 h1.83
  text "2" at 174.681,82.704 h1.52
  text "1.980mm (77.95mil)" at 183.114,82.704 h1.52
  text "NPTH" at 199.283,82.704 h1.52
  text "Round" at 205.865,82.704 h1.52
  text "Top Layer - Bottom Layer" at 215.394,82.704 h1.52
  text "C" at 166.405,82.451 h1.4
  text "1" at 174.681,79.547 h1.52
  text "2.080mm (81.89mil)" at 183.114,79.547 h1.52
  text "NPTH" at 199.283,79.547 h1.52
  text "Round" at 205.865,79.547 h1.52
  text "Top Layer - Bottom Layer" at 215.394,79.547 h1.52
  text "D" at 166.405,79.293 h1.4
  text "24" at 174.681,76.389 h1.52
  text "0.200mm (7.87mil)" at 183.114,76.389 h1.52
  text "PTH" at 199.283,76.389 h1.52
  text "Round" at 205.865,76.389 h1.52
  text "Top Layer - Bottom Layer" at 215.394,76.389 h1.52
  text "4" at 174.681,73.231 h1.52
  text "0.203mm (8.00mil)" at 183.114,73.231 h1.52
  text "PTH" at 199.283,73.231 h1.52
  text "Round" at 205.865,73.231 h1.52
  text "Top Layer - Bottom Layer" at 215.394,73.231 h1.52
  text "J" at 166.405,72.977 h1.4
  text "1001" at 174.681,70.073 h1.52
  text "0.254mm (10.00mil)" at 183.114,70.073 h1.52
  text "PTH" at 199.283,70.073 h1.52
  text "Round" at 205.865,70.073 h1.52
  text "Top Layer - Bottom Layer" at 215.394,70.073 h1.52
  text "12" at 174.681,66.916 h1.52
  text "0.300mm (11.81mil)" at 183.114,66.916 h1.52
  text "PTH" at 199.283,66.916 h1.52
  text "Round" at 205.865,66.916 h1.52
  text "Top Layer - Bottom Layer" at 215.394,66.916 h1.52
  text "6" at 174.681,63.758 h1.52
  text "0.450mm (17.72mil)" at 183.114,63.758 h1.52
  text "PTH" at 199.283,63.758 h1.52
  text "Round" at 205.865,63.758 h1.52
  text "Top Layer - Bottom Layer" at 215.394,63.758 h1.52
  text "12" at 174.681,60.6 h1.52
  text "0.610mm (24.00mil)" at 183.114,60.6 h1.52
  text "PTH" at 199.283,60.6 h1.52
  text "Round" at 205.865,60.6 h1.52
  text "Top Layer - Bottom Layer" at 215.394,60.6 h1.52
  text "6" at 174.681,57.442 h1.52
  text "0.660mm (26.00mil)" at 183.114,57.442 h1.52
  text "PTH" at 199.283,57.442 h1.52
  text "Round" at 205.865,57.442 h1.52
  text "Top Layer - Bottom Layer" at 215.394,57.442 h1.52
  text "3" at 174.681,54.285 h1.52
  text "0.813mm (32.00mil)" at 183.114,54.285 h1.52
  text "PTH" at 199.283,54.285 h1.52
  text "Round" at 205.865,54.285 h1.52
  text "Top Layer - Bottom Layer" at 215.394,54.285 h1.52
  text "A" at 166.405,54.031 h1.4
  text "10" at 174.681,51.127 h1.52
  text "0.900mm (35.43mil)" at 183.114,51.127 h1.52
  text "PTH" at 199.283,51.127 h1.52
  text "Round" at 205.865,51.127 h1.52
  text "Top Layer - Bottom Layer" at 215.394,51.127 h1.52
  text "87" at 174.681,47.969 h1.52
  text "1.016mm (40.00mil)" at 183.114,47.969 h1.52
  text "PTH" at 199.283,47.969 h1.52
  text "Round" at 205.865,47.969 h1.52
  text "Top Layer - Bottom Layer" at 215.394,47.969 h1.52
  text "28" at 174.681,44.812 h1.52
  text "1.040mm (40.95mil)" at 183.114,44.812 h1.52
  text "PTH" at 199.283,44.812 h1.52
  text "Round" at 205.865,44.812 h1.52
  text "Top Layer - Bottom Layer" at 215.394,44.812 h1.52
  text "G" at 166.405,44.558 h1.4
  text "12" at 174.681,41.654 h1.52
  text "1.050mm (41.34mil)" at 183.114,41.654 h1.52
  text "PTH" at 199.283,41.654 h1.52
  text "Round" at 205.865,41.654 h1.52
  text "Top Layer - Bottom Layer" at 215.394,41.654 h1.52
  text "2" at 174.681,38.496 h1.52
  text "1.092mm (43.00mil)" at 183.114,38.496 h1.52
  text "PTH" at 199.283,38.496 h1.52
  text "Round" at 205.865,38.496 h1.52
  text "Top Layer - Bottom Layer" at 215.394,38.496 h1.52
  text "B" at 166.405,38.242 h1.4
  text "8" at 174.681,35.338 h1.52
  text "1.350mm (53.15mil)" at 183.114,35.338 h1.52
  text "PTH" at 199.283,35.338 h1.52
  text "Round" at 205.865,35.338 h1.52
  text "Top Layer - Bottom Layer" at 215.394,35.338 h1.52
  text "6" at 174.681,32.181 h1.52
  text "1.600mm (63.00mil)" at 183.114,32.181 h1.52
  text "PTH" at 199.283,32.181 h1.52
  text "Round" at 205.865,32.181 h1.52
  text "Top Layer - Bottom Layer" at 215.394,32.181 h1.52
  text "2" at 174.681,29.023 h1.52
  text "2.080mm (81.89mil)" at 183.114,29.023 h1.52
  text "PTH" at 199.283,29.023 h1.52
  text "Round" at 205.865,29.023 h1.52
  text "Top Layer - Bottom Layer" at 215.394,29.023 h1.52
  text "F" at 166.405,28.769 h1.4
  text "1" at 174.681,25.865 h1.52
  text "2.870mm (112.99mil)" at 183.114,25.865 h1.52
  text "PTH" at 199.283,25.865 h1.52
  text "Round" at 205.865,25.865 h1.52
  text "Top Layer - Bottom Layer" at 215.394,25.865 h1.52
  text "E" at 166.405,25.611 h1.4
  text "2" at 174.681,22.707 h1.52
  text "3.250mm (127.95mil)" at 183.114,22.707 h1.52
  text "PTH" at 199.283,22.707 h1.52
  text "Round" at 205.865,22.707 h1.52
  text "Top Layer - Bottom Layer" at 215.394,22.707 h1.52
  text "K" at 166.405,22.454 h1.4
  text "5" at 174.681,19.55 h1.52
  text "3.600mm (141.73mil)" at 183.114,19.55 h1.52
  text "PTH" at 199.283,19.55 h1.52
  text "Round" at 205.865,19.55 h1.52
  text "Top Layer - Bottom Layer" at 215.394,19.55 h1.52
  text "I" at 166.639,19.296 h1.4
  text "2" at 174.681,16.392 h1.52
  text "3.658mm (144.00mil)" at 183.114,16.392 h1.52
  text "PTH" at 199.283,16.392 h1.52
  text "Round" at 205.865,16.392 h1.52
  text "Top Layer - Bottom Layer" at 215.394,16.392 h1.52
  text "6" at 174.681,13.234 h1.52
  text "4.953mm (195.00mil)" at 183.114,13.234 h1.52
  text "PTH" at 199.283,13.234 h1.52
  text "Round" at 205.865,13.234 h1.52
  text "Top Layer - Bottom Layer" at 215.394,13.234 h1.52
  text "H" at 166.405,12.98 h1.4
  text "2" at 174.681,10.077 h1.52
  text "0.800mm (31.50mil)" at 183.114,10.077 h1.52
  text "PTH" at 199.283,10.077 h1.52
  text "Slot" at 205.865,10.077 h1.52
  text "Top Layer - Bottom Layer" at 215.394,10.077 h1.52
  text "2" at 174.681,6.919 h1.52
  text "0.800mm (31.50mil)" at 183.114,6.919 h1.52
  text "PTH" at 199.283,6.919 h1.52
  text "Slot" at 205.865,6.919 h1.52
  text "Top Layer - Bottom Layer" at 215.394,6.919 h1.52
  text "1246 Total" at 174.681,3.761 h1.52
  text "Slot definitions :" at 167.047,1.551 h1.52
  text "Routed Path Length" at 178.495,1.551 h1.52
  text "= Calculated from tool start centre position to tool end centre position." at 192.205,1.551 h1.52
  text "Hole Length" at 178.495,0.288 h1.52
  text "= Routed Path Length + Tool Size = Slot length as defined in the PCB layout" at 187.13,0.288 h1.52
  text ".Layer_Name" at 14.656,-21.806 h1.52
Grids:
  lines w0.254: 62,62.5 150,62.5 ; 72,52.5 72,71.5
Heat Sink:
  lines w0.25: 53.75,26.375 90.25,26.375 90.25,104.875 53.75,104.875 53.75,26.375 ; 67,42.25 67,52.25 77,52.25 77,42.25 67,42.25 ; 67,79 67,89 77,89 77,79 67,79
